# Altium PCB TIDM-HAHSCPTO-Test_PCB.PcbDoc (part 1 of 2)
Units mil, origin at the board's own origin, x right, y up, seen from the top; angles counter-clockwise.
Board outline 6700 x 4350 mil, 2 copper layers (Top Layer, Bottom Layer), stack 62 mil thick; 37 components, 162 nets, 491 pads, 55 vias.
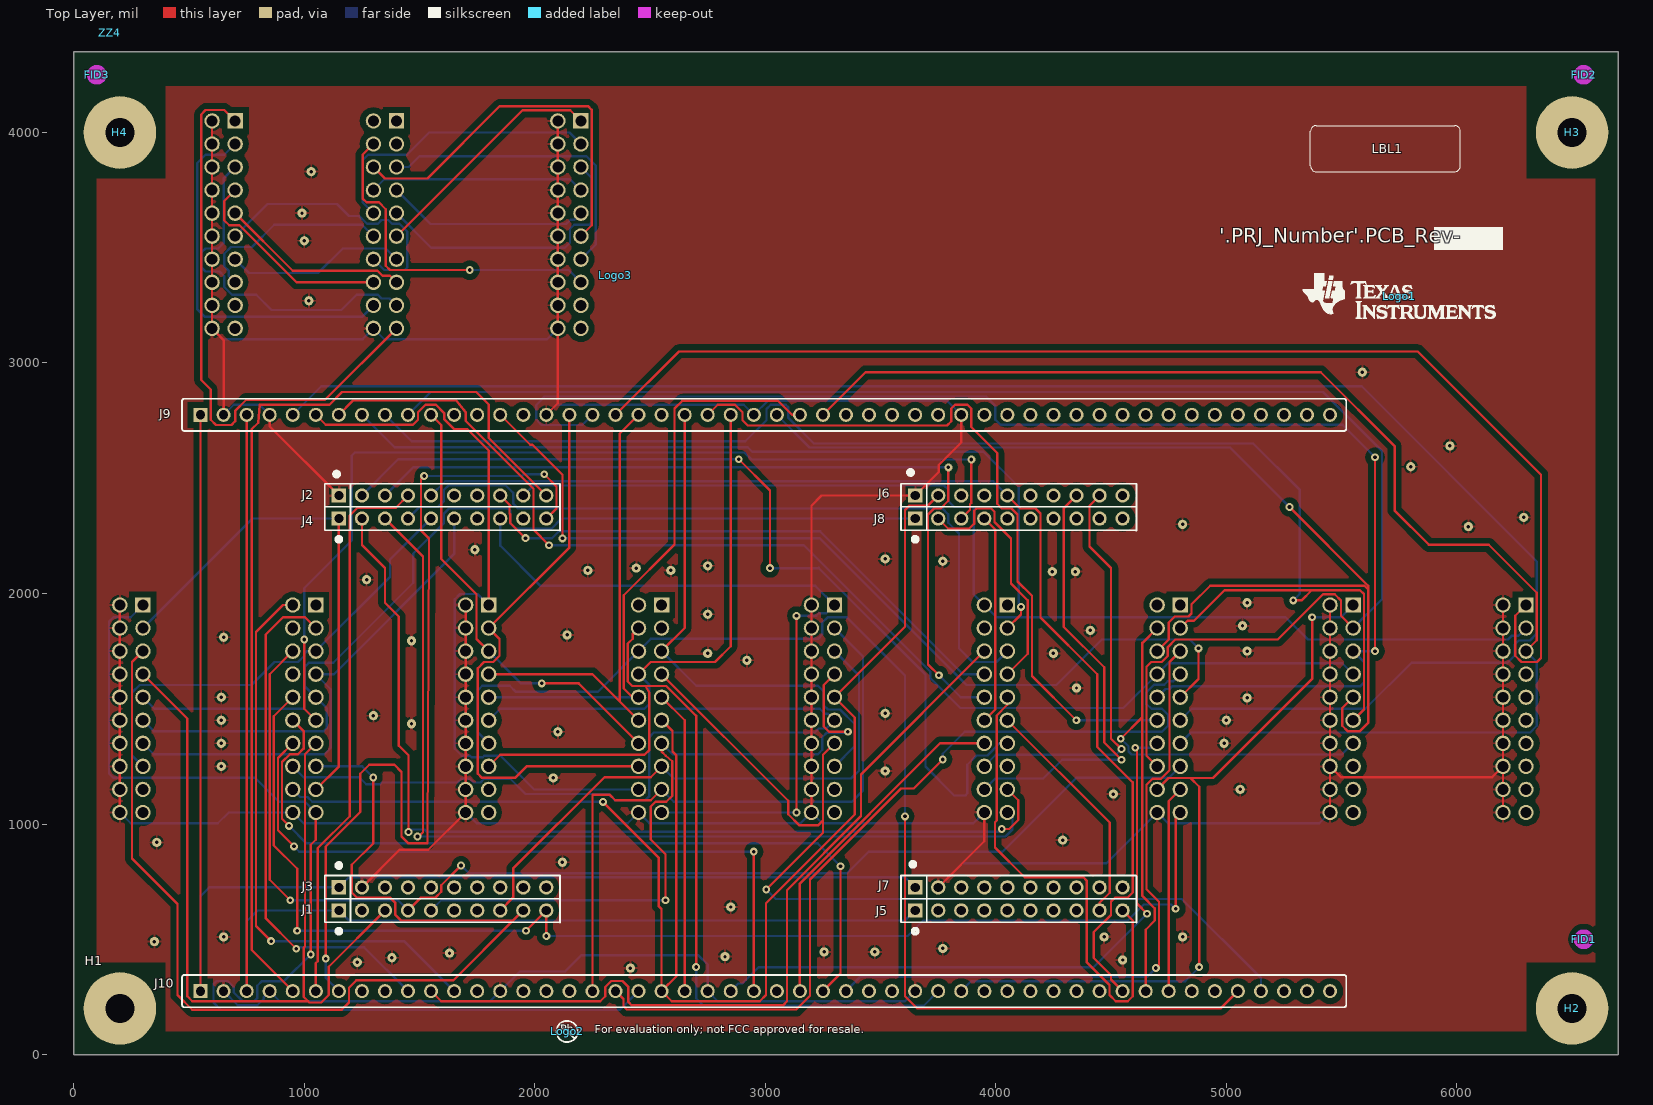
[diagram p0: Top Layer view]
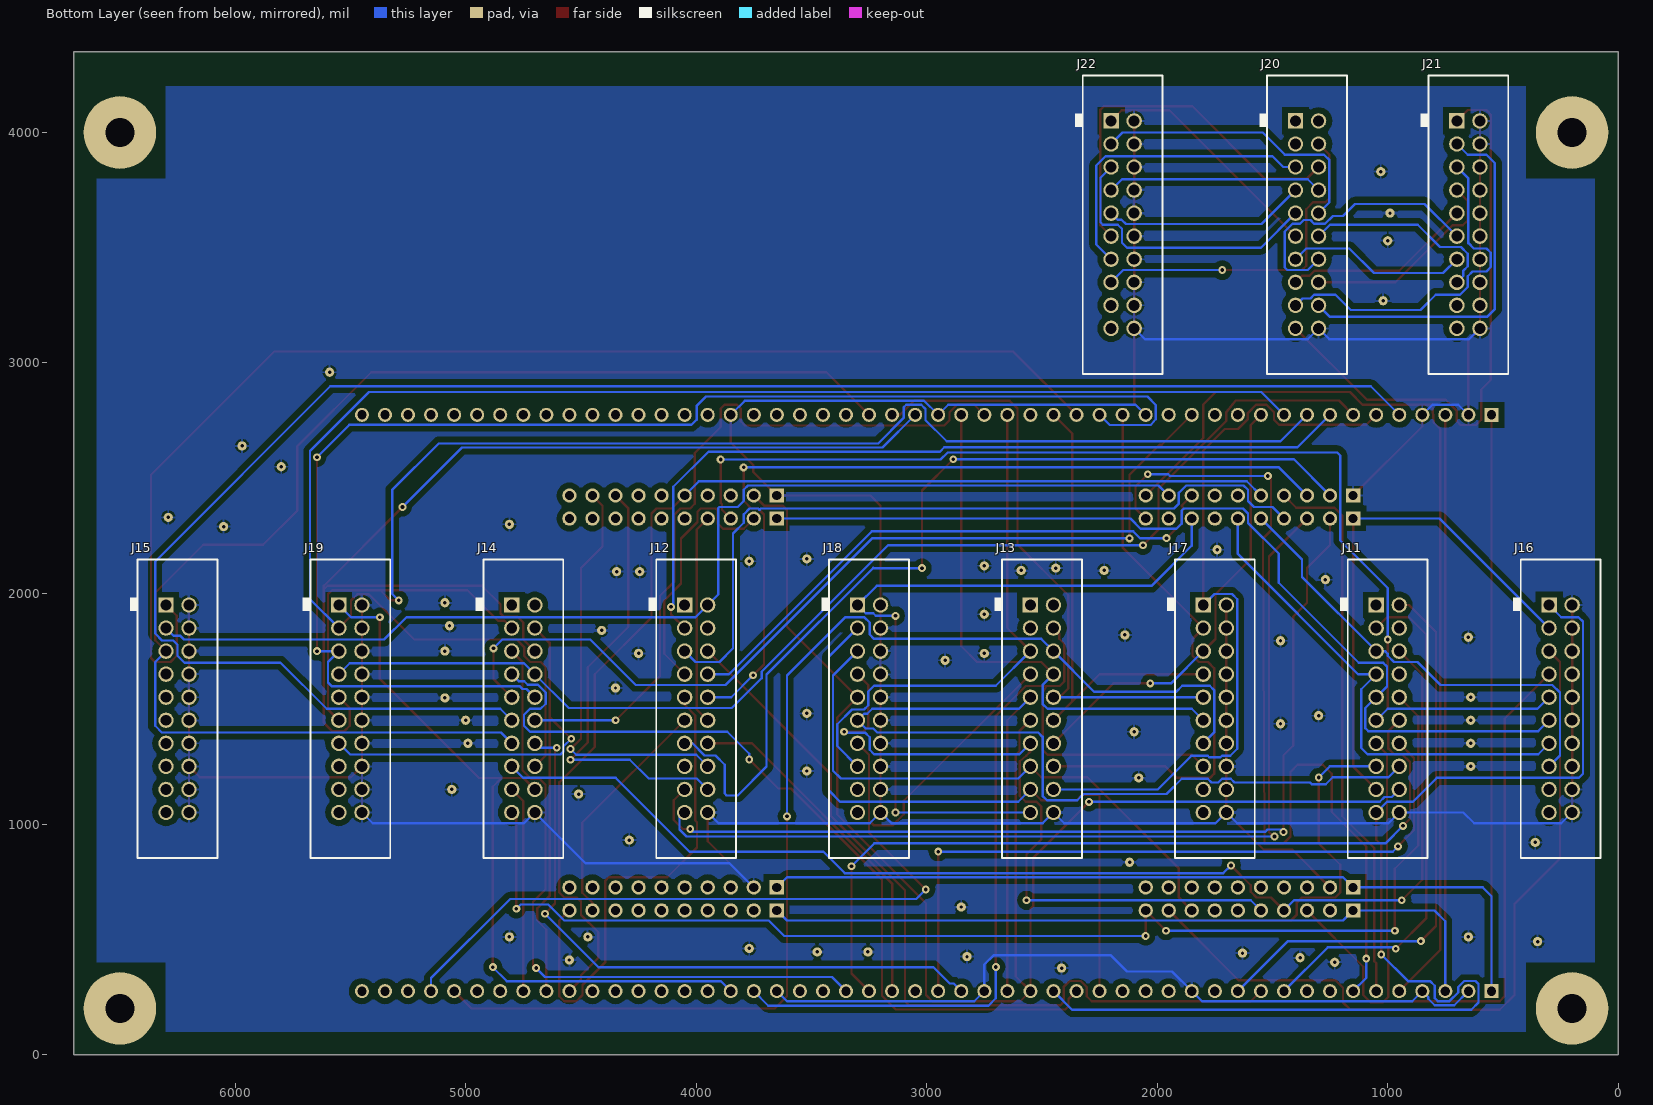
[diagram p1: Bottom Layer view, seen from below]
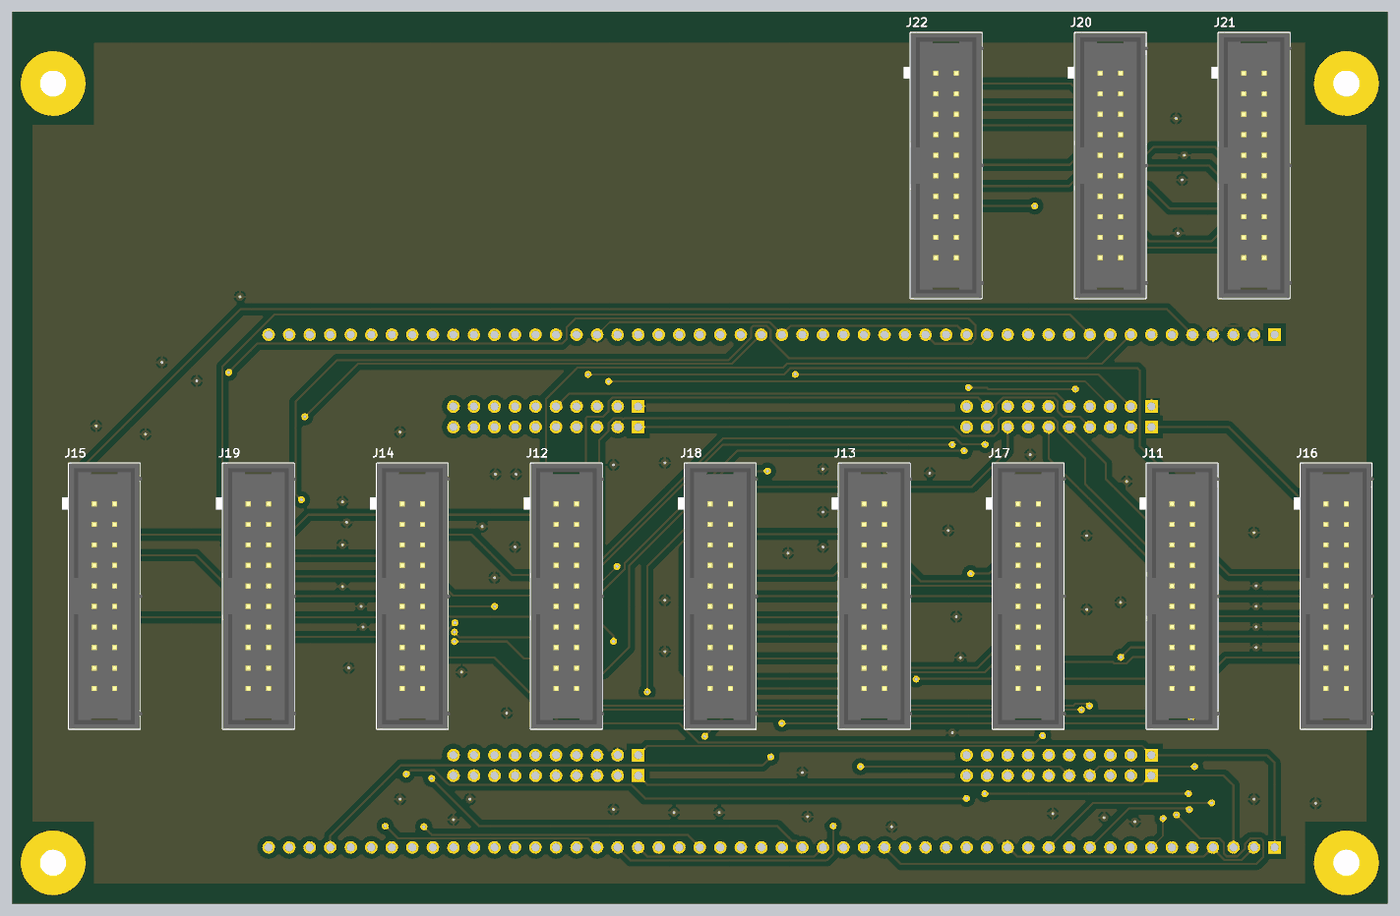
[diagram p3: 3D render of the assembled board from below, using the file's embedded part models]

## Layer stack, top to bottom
Top Solder: solder mask 0.4, Solder Resist, Dk 3.5
Top Layer: signal copper 1.4
Dielectric1: core 59.2, FR-4, Dk 4.8
Bottom Layer: signal copper 1.4
Bottom Solder: solder mask 0.4, Solder Resist, Dk 3.5

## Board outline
0,0 6700,0 6700,4350 0,4350

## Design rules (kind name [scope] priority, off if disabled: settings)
AcuteAngle [All] p1: minimum=4.50000000000000E+0001 checktracksonly=FALSE
AssemblyTestPointUsage [All] p1: valid=2
BoardOutlineClearance BoardOutlineClearance_MountingHoles [OnCopper and InComponentClass('Mounting Holes')] p1: gap=40
BoardOutlineClearance BoardOutlineClearance_Poly [OnCopper and InPoly] p2: gap=25
BoardOutlineClearance [OnCopper and Not InComponentClass('Logo') and not InComponentClass('FiducialMark') and not InRegion(1000,500,4000,800)] p3: gap=75
Clearance Clearance_Keepouts [((IsTrack Or IsArc) And Not InPoly) And IsFree and IsKeepOut vs ((IsTrack Or IsArc) And Not InPoly) And IsFree and IsKeepOut] p1: gap=0
Clearance Clearance_Poly [InPolygon] p2: gap=25
Clearance [All] p3: gap=7.87
ComponentClearance ComponentClearanceJ1J3 [InComponent('J1') vs InComponent('J3')] p1: gap=0 collisioncheckmode=3 verticalgap=10 showdistances=FALSE
ComponentClearance ComponentClearanceJ2J4 [InComponent('J2') vs InComponent('J4')] p2: gap=0 collisioncheckmode=3 verticalgap=10 showdistances=FALSE
ComponentClearance ComponentClearanceJ5J7 [InComponent('J5') vs InComponent('J7')] p3: gap=0 collisioncheckmode=3 verticalgap=10 showdistances=FALSE
ComponentClearance ComponentClearanceJ6J8 [InComponent('J6') vs InComponent('J8')] p4: gap=0 collisioncheckmode=3 verticalgap=10 showdistances=FALSE
ComponentClearance ComponentClearanceAll [All] p5: gap=10 collisioncheckmode=3 verticalgap=10 showdistances=FALSE
ComponentClearance ComponentClearance_MountingHoles_FiducialMarks [InComponentClass('Mounting Holes') vs InComponentClass('FiducialMark')] p6: gap=50 collisioncheckmode=3 verticalgap=10 showdistances=FALSE
ComponentClearance ComponentClearance_Shunt [InComponentClass('Header') vs InComponentClass('Shunt')] p7: gap=0 collisioncheckmode=3 verticalgap=0 showdistances=FALSE
ComponentClearance ComponentClearance_Logo [InComponentClass('Logo')] p8: gap=50 collisioncheckmode=3 verticalgap=10 showdistances=FALSE
ComponentClearance ComponentClearance_ScrewToNut [(HasFootprint('NY PMS 440 0025 PH')) vs (HasFootprint('Keystone_1902C'))] p9: gap=5 collisioncheckmode=3 verticalgap=10 showdistances=FALSE
ComponentClearance ComponentClearance_MountingHoles [InComponentClass('Mounting Holes')] p10: gap=250 collisioncheckmode=3 verticalgap=100000 showdistances=FALSE
ComponentClearance ComponentClearance_SmallPassives [HasFootprint('0201*') or HasFootprint('0402*') or HasFootprint('0508') or HasFootprint('0603*') or HasFootprint('0612') or HasFootprint('0805*') or HasFootprint('0815*') or HasFootprint('0830*') or HasFootprint('1206*') or HasFootprint('1210*') or HasFootprint('1808*') or HasFootprint('1812*') or HasFootprint('1825*') or HasFootprint('2010*') or HasFootprint('2220*') or HasFootprint('2225*') or HasFootprint('2512*') or HasFootprint('2728*') or HasFootprint('3518*') vs HasFootprint('0201*') or HasFootprint('0402*') or HasFootprint('0508') or HasFootprint('0603*') or HasFootprint('0612') or HasFootprint('0805*') or HasFootprint('0815*') or HasFootprint('0830*') or HasFootprint('1206*') or HasFootprint('1210*') or HasFootprint('1808*') or HasFootprint('1812*') or HasFootprint('1825*') or HasFootprint('2010*') or HasFootprint('2220*') or HasFootprint('2225*') or HasFootprint('2512*') or HasFootprint('2728*') or HasFootprint('3518*')] p11: gap=14.96 collisioncheckmode=3 verticalgap=10 showdistances=FALSE
ComponentClearance ComponentClearance_THtoSMT [IsThruComponent vs IsSMTComponent] p12: gap=40 collisioncheckmode=3 verticalgap=30 showdistances=FALSE
ComponentClearance ComponentClearance_THtoTH [IsThruComponent vs IsThruComponent] p13: gap=30 collisioncheckmode=3 verticalgap=30 showdistances=FALSE
DiffPairsRouting [All] p1: maxlimit=100 minlimit=10 mostfreqgap=10 toplayer_minwidth=15 toplayer_maxwidth=15 toplayer_prefwidth=15 bottomlayer_minwidth=15 bottomlayer_maxwidth=15 bottomlayer_prefwidth=15 maxuncoupledlength=1000
FabricationTestPointUsage TestPointUsage [All] p1: valid=2 allowmultiple=FALSE
FabricationTestpoint Testpoint [All] p1: side=3 testpointundercomponent=TRUE minsize=40 maxsize=100 preferedsize=60 minholesize=0 maxholesize=40 preferedholesize=32 testpointgrid=1 allowsidetop=TRUE allowsidebottom=TRUE usegrid=TRUE gridtolerance=0.01
FanoutControl Fanout_LCC [IsLCC] p1: bgadir=Out bgaviamode=Centered fanoutstyle=Auto fanoutdirection=Alternating viagrid=1 // Fanout_LCC (Default Rule)
FanoutControl Fanout_BGA [IsBGA] p2: bgadir=Out bgaviamode=Centered fanoutstyle=Auto fanoutdirection=Alternating viagrid=1 // Fanout_BGA (Default Rule)
FanoutControl Fanout_Default [All] p4: bgadir=Out bgaviamode=Centered fanoutstyle=Auto fanoutdirection=Alternating viagrid=1 // Fanout_Default (Default Rule)
FanoutControl Fanout_Small [(CompPinCount < 5)] p5: bgadir=Out bgaviamode=Centered fanoutstyle=Auto fanoutdirection=OutThenIn viagrid=1 // Fanout_Small (Default Rule)
HoleSize [All] p1: absolutevalues=TRUE maxlimit=251 minlimit=7.87 maxpercent=80.000 minpercent=20.000
MinimumAnnularRing MinimumAnnularRing_ThermalPadVias [IsVia and InAnyComponent] p1: minimumring=5.91
MinimumAnnularRing [All] p2: minimumring=8
MinimumSolderMaskSliver MinimumSolderMaskSliver_Logo [InComponentClass('Logo') vs InComponentClass('Logo')] p1: minsoldermaskwidth=0.7
MinimumSolderMaskSliver [All] p2: minsoldermaskwidth=3.94
PlaneConnect [All] p1: planeconnectstyle=Relief reliefexpansion=10 reliefentries=4 reliefconductorwidth=10 reliefairgap=10
PolygonConnect [All] p1: connectstyle=Relief reliefconductorwidth=10 reliefentries=4 polygonreliefangle="90 Angle" airgapwidth=10
RoutingVias ThermalPadVias [IsVia and InAnyComponent] p1: holewidth=7.87 width=19.68 viastyle="Through Hole" minholewidth=7.87 minwidth=19.68 maxholewidth=12.99 maxwidth=23.62
RoutingVias [All] p2: holewidth=16 width=34 viastyle="Through Hole" minholewidth=7.87 minwidth=26 maxholewidth=40 maxwidth=65
SilkToBoardRegionClearance [Not ((IsComment or IsDesignator) And (Hide <> 'False')) and not InRegion(1000,500,4000,800)] p1:
SilkToSilkClearance SilkToSilkClearance_Pb-FreeLogo [(HasFootprint('Pb-Free_Overlay_Medium') OR HasFootprint('Pb-Free_Overlay_Small')) vs (HasFootprint('Pb-Free_Overlay_Medium') OR HasFootprint('Pb-Free_Overlay_Small'))] p1: silktosilkclearance=0
SilkToSilkClearance [All] p2: silktosilkclearance=4
SilkToSolderMaskClearance SilkToComponentPadClearance [IsPad and InAnycomponent] p1: minsilkscreentomaskgap=5 clearancetoexposedcopper=TRUE
SilkToSolderMaskClearance "Silk to Solder Mask Opening" [All] p2: minsilkscreentomaskgap=4 clearancetoexposedcopper=FALSE
SolderMaskExpansion [All] p1: expansion=1.97
Width [All] p1: maxlimit=100 minlimit=6 preferedwidth=10 checkconnectedcopper=TRUE
15 further rules are at their usual default settings.

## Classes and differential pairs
component class "Mounting Holes": H1 H2 H3 H4
component class FiducialMark: FID1 FID2 FID3
component class Logo: Logo1
component class TIDM-HAHSCPTO-Test_Hw: FID1 FID2 FID3 H1 H2 H3 H4 LBL1 Logo1 Logo2 Logo3 ZZ1 ZZ2 ZZ3 ZZ4
component class AssemblyNote: ZZ1 ZZ2 ZZ3 ZZ4
component class Label: LBL1
component class TIDM-HAHSCPTO-Test_BoosterPack: J1 J2 J3 J4 J5 J6 J7 J8
component class TIDM-HAHSCPTO-Test_LogicAna: J11 J12 J13 J14
component class TIDM-HAHSCPTO-Test_Monitor: J20 J21 J22
component class TIDM-HAHSCPTO-Test_PatGen: J15 J16 J17 J18 J19
component class TIDM-HAHSCPTO-Test_Proto: J9 J10

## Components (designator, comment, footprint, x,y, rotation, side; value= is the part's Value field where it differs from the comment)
FID1 "Fiducial" Fiducial10-20 6550,500 r0 top
FID2 "Fiducial" Fiducial10-20 6550,4250 r0 top
FID3 "Fiducial" Fiducial10-20 100,4250 r0 top
H1 "NY PMS 440 0025 PH" "NY PMS 440 0025 PH" 200,200 r0 top
H2 "NY PMS 440 0025 PH" "NY PMS 440 0025 PH" 6500,200 r0 top
H3 "NY PMS 440 0025 PH" "NY PMS 440 0025 PH" 6500,4000 r0 top
H4 "NY PMS 440 0025 PH" "NY PMS 440 0025 PH" 200,4000 r0 top
J1 "PPTC101LFBN-RC" CONN_PPTC101LFBN-RC 1600,625 r180 top
J2 "PPTC101LFBN-RC" CONN_PPTC101LFBN-RC 1600,2425 r180 top
J3 "PPTC101LFBN-RC" CONN_PPTC101LFBN-RC 1600,725 r180 top
J4 "PPTC101LFBN-RC" CONN_PPTC101LFBN-RC 1600,2325 r180 top
J5 "PPTC101LFBN-RC" CONN_PPTC101LFBN-RC 4100,625 r180 top
J6 "PPTC101LFBN-RC" CONN_PPTC101LFBN-RC 4100,2425 r180 top
J7 "PPTC101LFBN-RC" CONN_PPTC101LFBN-RC 4100,725 r180 top
J8 "PPTC101LFBN-RC" CONN_PPTC101LFBN-RC 4100,2325 r180 top
J9 "SFH11-PBPC-D25-ST-BK" SFH11-PBPC-D25-ST-BK 3000,2775 r0 top
J10 "SFH11-PBPC-D25-ST-BK" SFH11-PBPC-D25-ST-BK 3000,275 r0 top
J11 "SBH11-PBPC-D10-ST-BK" Sullins_SBH11-xxxC-D10-ST 1000,1500 r180 bottom
J12 "SBH11-PBPC-D10-ST-BK" Sullins_SBH11-xxxC-D10-ST 4000,1500 r180 bottom
J13 "SBH11-PBPC-D10-ST-BK" Sullins_SBH11-xxxC-D10-ST 2500,1500 r180 bottom
J14 "SBH11-PBPC-D10-ST-BK" Sullins_SBH11-xxxC-D10-ST 4750,1500 r180 bottom
J15 "SBH11-PBPC-D10-ST-BK" Sullins_SBH11-xxxC-D10-ST 6250,1500 r180 bottom
J16 "SBH11-PBPC-D10-ST-BK" Sullins_SBH11-xxxC-D10-ST 250,1500 r180 bottom
J17 "SBH11-PBPC-D10-ST-BK" Sullins_SBH11-xxxC-D10-ST 1750,1500 r180 bottom
J18 "SBH11-PBPC-D10-ST-BK" Sullins_SBH11-xxxC-D10-ST 3250,1500 r180 bottom
J19 "SBH11-PBPC-D10-ST-BK" Sullins_SBH11-xxxC-D10-ST 5500,1500 r180 bottom
J20 "SBH11-PBPC-D10-ST-BK" Sullins_SBH11-xxxC-D10-ST 1350,3600 r180 bottom
J21 "SBH11-PBPC-D10-ST-BK" Sullins_SBH11-xxxC-D10-ST 650,3600 r180 bottom
J22 "SBH11-PBPC-D10-ST-BK" Sullins_SBH11-xxxC-D10-ST 2150,3600 r180 bottom
LBL1 "Size: 0.65\" x 0.20 \"" Label_650x200 5690,3930 r0 top
Logo1 "Texas Instruments" TI_Stacked_Overlay_Small 5750,3290 r0 top
Logo2 "Pb-Free Symbol" Pb-Free_Overlay_Small 2140,100 r0 top
Logo3 "FCC disclaimer" FCC_disclaimer 2350,3380 r0 top
ZZ1 "This Assembly Note is for PCB labels only" AssemblyNoteLabel 155,4718 r0 top
ZZ2 "These assemblies are ESD sensitive, ESD precautions shall be observed." AssemblyNote 155,4609.11 r0 top
ZZ3 "These assemblies must be clean and free from flux and all contaminants. Use of no clean flux is not acceptable." AssemblyNote 155,4520.56 r0 top
ZZ4 "These assemblies must comply with workmanship standards IPC-A-610 Class 2, unless otherwise specified." AssemblyNote 155,4432 r0 top

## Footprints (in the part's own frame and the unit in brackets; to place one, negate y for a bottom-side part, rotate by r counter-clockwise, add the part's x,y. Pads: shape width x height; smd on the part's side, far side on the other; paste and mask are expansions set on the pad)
AssemblyNote [mil] "Assembly Note"
AssemblyNoteLabel [mil] "Assembly Note for PCB Labels"
CONN_PPTC101LFBN-RC [mil] "SULLINS"
  rect 62x62 hole 40: 1(450,0)
  round 62 hole 40.16: 2(350,0) 3(250,0) 4(150,0) 5(50,0) 6(-50,0) 7(-150,0) 8(-250,0) 9(-350,0) 10(-450,0)
  silkscreen extent -510,-51 511,100, body extent -510,-50 510,50, height 336
FCC_disclaimer [mil]
Fiducial10-20 [mm]
  round 1 smd mask+0.5: 1(0,0)
  Top Layer keep-out circle w1.178: c0,0 r0.5
Label_650x200 [mil] "Thermal Transfer Label"
  silkscreen extent -325,-100 325,100, body extent -325,-100 325,100, height 1
"NY PMS 440 0025 PH" [mm] "4-40 nylon screw and mounting hole"
  round 8 hole 3.2: 1(0,0)
  body extent -3.3,-3.3 3.3,3.3, height 2.69
Pb-Free_Overlay_Small [mil]
  silkscreen extent -46,-46 46,46
SFH11-PBPC-D25-ST-BK [mm]
  rect 1.55x1.55 hole 1.02: 1(-62.23,0)
  round 1.55 hole 1.02: 2(-59.69,0) 3(-57.15,0) 4(-54.61,0) 5(-52.07,0) 6(-49.53,0) 7(-46.99,0) 8(-44.45,0) 9(-41.91,0) 10(-39.37,0) 11(-36.83,0) 12(-34.29,0) 13(-31.75,0) 14(-29.21,0) 15(-26.67,0) 16(-24.13,0) 17(-21.59,0) 18(-19.05,0) 19(-16.51,0) 20(-13.97,0) 21(-11.43,0) 22(-8.89,0) 23(-6.35,0) 24(-3.81,0) 25(-1.27,0) 26(1.27,0) 27(3.81,0) 28(6.35,0) 29(8.89,0) 30(11.43,0) 31(13.97,0) 32(16.51,0) 33(19.05,0) 34(21.59,0) 35(24.13,0) 36(26.67,0) 37(29.21,0) 38(31.75,0) 39(34.29,0) 40(36.83,0) 41(39.37,0) 42(41.91,0) 43(44.45,0) 44(46.99,0) 45(49.53,0) 46(52.07,0) 47(54.61,0) 48(57.15,0) 49(59.69,0) 50(62.23,0)
  silkscreen extent -64.26,-1.78 64.01,1.78
Sullins_SBH11-xxxC-D10-ST [mm] "Header (Shrouded), 2.54mm, 10x2, TH"
  rect 1.7x1.7 hole 1.2: 1(-1.27,11.43)
  round 1.7 hole 1.2: 2(1.27,11.43) 3(-1.27,8.89) 4(1.27,8.89) 5(-1.27,6.35) 6(1.27,6.35) 7(-1.27,3.81) 8(1.27,3.81) 9(-1.27,1.27) 10(1.27,1.27) 11(-1.27,-1.27) 12(1.27,-1.27) 13(-1.27,-3.81) 14(1.27,-3.81) 15(-1.27,-6.35) 16(1.27,-6.35) 17(-1.27,-8.89) 18(1.27,-8.89) 19(-1.27,-11.43) 20(1.27,-11.43)
  silkscreen extent -5.25,-16.45 4.4,16.45, body extent -4.4,-16.45 4.7,16.45, height 9.11
TI_Stacked_Overlay_Small [mil]
  silkscreen extent -418,-98 418,98

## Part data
FID1 FID2 FID3: "Fiducial mark.  There is nothing to buy or mount."
H1 H2 H3 H4: "Machine Screw, Round, #4-40 x 1/4, Nylon, Philips panhead"
J1 J2 J3 J4 J5 J6 J7 J8: "Receptacle, 100mil, 10x1, Tin, TH"
J9 J10: ".100\" 1 Row, Thru Hole with Polarizing Key"
J11 J12 J13 J14 J15 J16 J17 J18 J19 J20 J21 J22: "Header (Shrouded), 2.54mm, 10x2, Gold, Black, TH"
LBL1: library part THT-14-423-10, "Thermal Transfer Printable Labels, 0.650\" W x 0.200\" H - 10,000 per roll"
Logo1: library part TI_Logo, "Texas Instrument Corporate Signature"
Logo2: library part Pb-Free
Logo3: library part FCC_disclaimer, "FCC_disclaimer"
ZZ1: library part AssemblyNoteLabel
ZZ2 ZZ3 ZZ4: library part AssemblyNote

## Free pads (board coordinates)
  round 40 hole 15: 2(650,1810) 3(2140,1820) 4(1300,1470) 5(360,920) 5(990,3650) 5(1000,3530) 5(1020,3270) 5(1030,3830) 5(1465,1435) 5(1465,1795) 5(1740,2190) 5(2080,1200) 5(2100,1400) 5(2120,834) 5(2415,375) 5(2440,2110) 5(2590,2100) 5(2750,1740) 5(2750,1910) 5(2750,2120) 5(2825,425) 5(2920,1710) 5(3255,445) 5(3475,445) 5(3770,460) 5(4245,2095) 5(4345,2095) 5(4990,1350) 5(5000,1450) 5(5060,1150) 5(5070,1860) 5(5090,1547) 5(5090,1750) 5(5090,1960) 5(5590,2960) 5(5800,2550) 5(5970,2640) 5(6050,2290) 5(6290,2330) 6(2850,640) 7(4810,2300) 8(4350,1590) 9(3520,1480) 10(3520,1230) 11(4510,1130) 12(4290,930) 13(4810,510) 14(4550,410) 15(4470,510) 16(640,1250) 17(640,1450) 18(640,1350) 19(640,1550) 20(350,490) 21(650,510) 22(1630,440) 23(1380,420) 24(1230,400) 25(2230,2100) 27(1270,2060) 28(4250,1740) 29(4410,1840) 30(3520,2150) 32(3770,2140)

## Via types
v1: diameter 34, hole 16, Top Layer to Bottom Layer, 55 vias

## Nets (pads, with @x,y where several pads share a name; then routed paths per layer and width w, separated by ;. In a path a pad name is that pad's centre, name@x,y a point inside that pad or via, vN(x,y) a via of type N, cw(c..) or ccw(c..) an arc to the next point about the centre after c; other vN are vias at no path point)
+3V3: J1.1 J5.1 J9.3 J10.3 | length 5758.9
  Top Layer w10: J10.3@750,275 J9.3@750,2775
  Bottom Layer w10: J10.3@750,275 750,578 797,625 J1.1@1150,625 1194,581 3606,581 J5.1@3650,625
+5V: J3.1 J7.1 J9.1 J10.1 | length 6064.2
  Top Layer w10: J10.1@550,275 J9.1@550,2775
  Bottom Layer w10: J10.1@550,275 550,687 588,725 J3.1@1150,725 1194,769 3606,769 J7.1@3650,725
AD1EVT/MII_RX_ER/RMII_RX_ER/NTZ1_1: J8.9
AD1IN_0: J3.3
AD1IN_1: J5.6
AD1IN_2: J7.4
AD1IN_3: J7.5
AD1IN_4: J7.7
AD1IN_5: J9.47
AD1IN_6: J9.48
AD1IN_7: J3.4
AD1IN_8/AD2IN_8: J9.43
AD1IN_9/AD2IN_9: J5.2
AD1IN_10/AD2IN_10: J7.3
AD1IN_11/AD2IN_11: J7.6
AD1IN_12/AD2IN_12: J7.8
AD1IN_13/AD2IN_13: J9.46
AD1IN_14/AD2IN_14: J9.44
AD1IN_15/AD2IN_15: J9.41
AD1IN_16/AD2IN_0: J1.2
AD1IN_17/AD2IN_1: J1.6
AD1IN_18/AD2IN_2: J3.5
AD1IN_19/AD2IN_3: J3.6
AD1IN_20/AD2IN_4: J3.7
AD1IN_21/AD2IN_5: J3.8
AD1IN_22/AD2IN_6: J9.45
AD1IN_23/AD2IN_7: J9.42
AD1IN_24: J9.49
AD1IN_25: J9.50
AD1IN_26: J9.31
AD1IN_27: J9.32
AD1IN_28: J9.33
AD1IN_29: J9.35
AD1IN_30: J9.36
AD1IN_31: J9.37
AD2EVT: J9.40
AD2IN_23: J9.29
AD2IN_24: J9.30
ADREFHI: J9.39
ADREFLO: J9.38
DCAN1RX: J10.44
DCAN1TX: J10.45
DCAN2RX: J9.12
DCAN2TX: J9.13
DCAN3RX: J10.13
DCAN3TX: J10.15
ECLK1T: J9.19 J15.1 | length 5515.2
  Top Layer w10: J9.19@2350,2775 2625,3050 5830,3050 6365,2515 6365,1720 6348,1703 6280,1703 6253,1730 6253,1903 J15.1@6300,1950
EPWM1A: J10.17
EPWM1B: J10.16
FRAYRX1: J10.35
FRAYRX2: J10.38
FRAYTX1/GIOA_2: J10.36
FRAYTX2/GIOB_0: J10.39
FRAYTXEN1/GIOB_1: J10.37
FRAYTXEN2/GIOB_2: J10.40
GIOA_0: J4.10 J10.7 | length 4012
  Top Layer w10: v1(1093,416) 1093,902 1243,1052 1243,1218 1282,1257 1391.25,1257 1422.13,1226.13 1422.13,945.71 1452,915.83 1534.15,915.83 1540.61,2238.39 1506,2273 1506,2496 v1(1520,2510) ; v1(2041,2517) 2094,2464 2094,2369 J4.10@2050,2325
  Bottom Layer w10: v1(1093,416) 1093,332 J10.7@1150,275 ; v1(1520,2510) 1945,2510 1952,2517 v1(2041,2517)
GIOA_1: J4.9
GIOA_2/N2HET2_0/EQEP2I: J4.8 J13.19 J18.1 | length 3296.5
  Top Layer w10: v1(3135,1050) v1(3135,1903)
  Bottom Layer w10: J4.8@1850,2325 1850,2207.64 2024.64,2033 3217,2033 J18.1@3300,1950 3264.21,1914.21 3232.13,1914.21 3220.91,1903 v1(3135,1903) ; J13.19@2550,1050 v1(3135,1050)
GIOA_3/N2HET2_2: J10.18 J13.17 J18.3 | length 2851.9
  Top Layer w10: J10.18@2250,275 2250,1125 2251.3,1126.3 2325.74,1126.3 2349.1,1102.94 2502.94,1102.94 J13.17@2550,1150
  Bottom Layer w10: J13.17@2550,1150 2603,1097 3376,1097 3423.96,1144.96 3423.96,1726.04 J18.3@3300,1850
GIOA_4: J9.15
GIOA_5/EXTCLKIN/EPWM1A: J4.7
GIOA_6/N2HET2_4/EPWM1B: J1.8 J13.15 J18.5 | length 2487.6
  Top Layer w10: J1.8@1850,625 1906,681 1906,806.83 2302.17,1203 2503,1203 J13.15@2550,1250
  Bottom Layer w10: J13.15@2550,1250 2603,1197 3372,1197 3406.09,1231.09 3406.09,1643.91 J18.5@3300,1750
GIOA_7/N2HET2_6/EPWM2A: J1.5 J13.13 J18.7 | length 3089.6
  Top Layer w10: J13.13@2550,1350 2550,1314 2567.66,1296.34 2596.34,1272 2596.34,1122 2570.68,1096.34 2524,1096.34 2503,1075.34 2503,933 2567,869 v1(2567,669) ; J18.7@3300,1650 3253,1603 3253,1423 3276,1400 v1(3358,1400)
  Bottom Layer w10: J1.5@1550,625 1594,669 v1(2567,669) ; J13.13@2550,1350 2597,1303 3228,1303 3247,1322 3247,1376 3267.34,1396.34 3354.34,1396.34 v1(3358,1400)
GIOB_0: J8.8
GIOB_1: J8.7
GIOB_2/DCAN4TX: J2.10 J10.5 | length 4166.3
  Top Layer w10: J10.5@950,275 772,453 772,2713 800,2741 807,2819 1109,2819 1164,2874 1746,2874 1800,2820 1800,2675 J2.10@2050,2425
GIOB_3/DCAN4RX: J2.4 J10.6 | length 2412.9
  Top Layer w10: J10.6@1050,275 1050,396.64 1058.31,404.96 1058.31,895.31 1197,1034 1197,2338 1231,2372 1397,2372 J2.4@1450,2425
GND: J2.1 J3.2 J6.1 J7.2 J9.2 J9.4 J9.16 J9.25 J9.34 J10.2 J10.4 J10.14 J10.23 J10.32 J11.20 J12.20 J13.20 J14.20 J15.2 J15.4 J15.6 J15.8 J15.10 J15.12 J15.14 J15.16 J15.18 J15.20 J16.2 J16.4 J16.6 J16.8 J16.10 J16.12 J16.14 J16.16 J16.18 J16.20 J17.2 J17.4 J17.6 J17.8 J17.10 J17.12 J17.14 J17.16 J17.18 J17.20 J18.2 J18.4 J18.6 J18.8 J18.10 J18.12 J18.14 J18.16 J18.18 J18.20 J19.2 J19.4 J19.6 J19.8 J19.10 J19.12 J19.14 J19.16 J19.18 J19.20 J20.20 J21.2 J21.4 J21.6 J21.8 J21.10 J21.12 J21.14 J21.16 J21.18 J21.20 J22.2 J22.4 J22.6 J22.8 J22.10 J22.12 J22.14 J22.16 J22.18 J22.20 pad.2 pad.3 pad.4 pad.5 pad.6 pad.7 pad.8 pad.9 pad.10 pad.11 pad.12 pad.13 pad.14 pad.15 pad.16 pad.17 pad.18 pad.19 pad.20 pad.21 pad.22 pad.23 pad.24 pad.25 pad.27 pad.28 pad.29 pad.30 pad.32 | length 23522.7
  Top Layer w10: J16.20@200,1050 J16.18@200,1150 J16.16@200,1250 J16.14@200,1350 J16.12@200,1450 J16.10@200,1550 J16.8@200,1650 J16.6@200,1750 J16.4@200,1850 J16.2@200,1950 ; J21.2@600,4050 J21.4@600,3950 J21.6@600,3850 J21.8@600,3750 J21.10@600,3650 J21.12@600,3550 J21.14@600,3450 J21.16@600,3350 J21.18@600,3250 J21.20@600,3150 650,3100 J9.2@650,2775 ; J9.4@850,2775 850,2725 J2.1@1150,2425 ; J3.2@1250,725 1413,888 1538,888 J17.20@1700,1050 J17.18@1700,1150 J17.16@1700,1250 J17.14@1700,1350 J17.12@1700,1450 J17.10@1700,1550 J17.8@1700,1650 J17.6@1700,1750 J17.4@1700,1850 J17.2@1700,1950 ; J9.16@2050,2775 2100,2825 J22.20@2100,3150 J22.18@2100,3250 J22.16@2100,3350 J22.14@2100,3450 J22.12@2100,3550 J22.10@2100,3650 J22.8@2100,3750 J22.6@2100,3850 J22.4@2100,3950 J22.2@2100,4050 ; J18.20@3200,1050 J18.18@3200,1150 J18.16@3200,1250 J18.14@3200,1350 J18.12@3200,1450 J18.10@3200,1550 J18.8@3200,1650 J18.6@3200,1750 J18.4@3200,1850 J18.2@3200,1950 3200,2381 3244,2425 J6.1@3650,2425 3752.05,2527.05 3752.05,2556.94 3850,2654.9 J9.34@3850,2775 ; J7.2@3750,725 3950,925 J12.20@3950,1050 ; J19.20@5450,1050 J19.18@5450,1150 J19.16@5450,1250 ; J19.2@5450,1950 J19.4@5450,1850 J19.6@5450,1750 J19.8@5450,1650 J19.10@5450,1550 J19.12@5450,1450 J19.14@5450,1350 J19.16@5450,1250 ; J15.20@6200,1050 J15.18@6200,1150 J15.16@6200,1250 ; J15.2@6200,1950 J15.4@6200,1850 J15.6@6200,1750 J15.8@6200,1650 J15.10@6200,1550 J15.12@6200,1450 J15.14@6200,1350 J15.16@6200,1250 ; J19.16@5450,1250 5497,1203 6153,1203 J15.16@6200,1250
  Bottom Layer w10: J16.20@200,1050 247,1003 625,1003 672,1050 J11.20@950,1050 997,1003 1653,1003 J17.20@1700,1050 1747,1003 2403,1003 J13.20@2450,1050 2497,1003 3153,1003 J18.20@3200,1050 3247,1003 3903,1003 J12.20@3950,1050 ; J21.20@600,3150 647,3103 1253,3103 J20.20@1300,3150 1347,3103 2053,3103 J22.20@2100,3150 ; J10.2@650,275 711.26,213.74 796.23,213.74 824.49,242 824.49,249.49 J10.4@850,275 894,231 1806,231 J10.14@1850,275 1935.26,360.26 2130.45,360.26 2200.18,430 2710,430 2750,390 J10.23@2750,275 2794,231 3606,231 J10.32@3650,275 ; J9.2@650,2775 694,2819 806,2819 J9.4@850,2775 ; J9.16@2050,2775 2094,2819 2906,2819 J9.25@2950,2775 3011.26,2836.26 3788.74,2836.26 J9.34@3850,2775 ; J7.2@3750,725 3855,830 4480,830 J14.20@4700,1050 4747,1003 5403,1003 J19.20@5450,1050
HERCULES_NRST: J2.5 J6.5 J10.41 | length 5119.2
  Top Layer w10: J6.5@4050,2425 4106.13,2368.87 4172,2368.87 4193.87,2347 4193.87,1896.13 4440,1650 4440,1334.5 4593.87,1180.63 4593.87,703 4572,681.13 4517.87,681.13 4500,663.25 4500,605.82 4424.13,529.96 4424.13,419.91 4500,344.05 4500,325 J10.41@4550,275
  Bottom Layer w10: J2.5@1550,2425 1611.75,2486.75 3988.25,2486.75 J6.5@4050,2425
LIN1RX: J5.3
LIN1TX: J5.4
MIBSPI1CLK: J5.7
MIBSPI1NCS_0/MIBSPI1SOMI_1/MII_TXD_2/ECAP6: J6.3
MIBSPI1NCS_1/MII_COL/N2HET1_17/EQEP1S: J6.8 J12.18 | length 1921.6
  Top Layer w10: J6.8@4350,2425 4294,2369 4294,1856 4470,1680 4470,1354 v1(4545,1279)
  Bottom Layer w10: J12.18@3950,1150 3997,1197 4206,1197 4288,1279 v1(4545,1279)
MIBSPI1NCS_2/MDIO/N2HET1_19: J6.9 J12.16 | length 1801.9
  Top Layer w10: J6.9@4450,2425 4406,2381 4406,2204 4500,2110 4500,1370 v1(4545,1325)
  Bottom Layer w10: J12.16@3950,1250 4000,1300 4520,1300 v1(4545,1325)
MIBSPI1NCS_3/N2HET1_21/NTZ1_3: J10.27 J12.14 | length 1518.7
  Top Layer w10: J10.27@3150,275 3150,741.73 3758.27,1350 J12.14@3950,1350
MIBSPI1NCS_4: J10.30
MIBSPI1NCS_5: J10.31
MIBSPI1NENA/MII_RXD_2/N2HET1_23/ECAP4: J8.4 J12.12 | length 913.9
  Top Layer w10: J12.12@3950,1450 3997,1497 3997,2278 J8.4@3950,2325
MIBSPI1SIMO_0: J6.6
MIBSPI1SOMI_0: J6.7
MIBSPI3CLK/AD1EXT_SEL_1/EQEP1A: J1.7
MIBSPI3NCS_0/AD2EVT/EQEP1I: J5.5
MIBSPI3NCS_1/MDCLK/N2HET1_25: J2.3 J12.10 | length 3705.8
  Top Layer w10: v1(3753,1645) 3706,1692 3706,2343.05 3731.83,2368.87 3760.87,2368.87 3794,2402 v1(3794,2547)
  Bottom Layer w10: J2.3@1350,2425 1472,2547 v1(3794,2547) ; v1(3753,1645) 3848,1550 J12.10@3950,1550
MIBSPI3NCS_2/I2C1_SDA/N2HET1_27/NTZ1_2: J2.8 J12.8 | length 2492.6
  Top Layer w10: J2.8@1850,2425 1894,2381 1890,2377 1890,2347.05 1893.87,2343.17 1893.87,2306.13 v1(1960,2240)
  Bottom Layer w10: v1(1960,2240) 2074.07,2240 2103.41,2269.34 3238.66,2269.34 3858,1650 J12.8@3950,1650
MIBSPI3NCS_3/I2C1_SCL/N2HET1_29/NTZ1_1: J2.9 J12.2 J15.3 | length 4914.3
  Bottom Layer w10: J2.9@1950,2425 1993.87,2468.87 3775.13,2468.87 3794,2450 3794,2401 3820,2375 3900,2375 3904,2371 3904,1996 J12.2@3950,1950 4003,1897 5257,1897 5354,1800 6221.57,1800 6237.57,1816 6266,1816 J15.3@6300,1850
MIBSPI3NENA/MIBSPI3NCS_5/N2HET1_31/EQEP1B: J5.8
MIBSPI3SIMO/AD1EXT_SEL_0/ECAP3: J2.6
MIBSPI3SOMI/AD1EXT_ENA/ECAP2: J2.7
MIBSPI5CLK/DMM_DATA_4/MII_TXEN/RMII_TXEN: J8.10
MIBSPI5NCS_0/DMM_DATA_5/EPWM4A: J10.26
MIBSPI5NENA/DMM_DATA_7/MII_RXD_3/ECAP5: J8.5
MIBSPI5SIMO_0/DMM_DATA_8/MII_TXD_1/RMII_TXD_1: J6.4
MIBSPI5SOMI_0/DMM_DATA_12/MII_TXD_0/RMII_TXD_0: J6.10
MON0: J20.19 J21.1 | length 2530.8
  Top Layer w10: J21.1@700,4050 653,4097 572,4097 553,4078 553,2926 594,2885 594,2754 617,2731 684,2731 700,2747 700,2792 748,2840 1090,2840 J20.19@1400,3150
MON1: J20.18 J21.3 | length 1631.6
  Bottom Layer w10: J21.3@700,3950 653,3903 572,3903 535,3866 535,3234 569,3200 1250,3200 J20.18@1300,3250
MON2: J20.17 J21.5 | length 1524.8
  Bottom Layer w10: J21.5@700,3850 650,3800 650,3520 627,3497 572,3497 553,3478 553,3416 572,3397 632,3397 653,3376 653,3330 686.66,3296.34 791.3,3296.34 857.64,3230 1160,3230 1226.34,3296.34 1319.19,3296.34 1335.53,3280 1370,3280 J20.17@1400,3250
MON3: J20.16 J21.7 | length 909.5
  Top Layer w10: J21.7@700,3750 653,3703 653,3618 674,3597 719,3597 966,3350 J20.16@1300,3350
MON4: J20.15 J21.9 | length 824.3
  Top Layer w10: J21.9@700,3650 950,3400 1317.91,3400 1339.8,3378.11 1371.89,3378.11 J20.15@1400,3350
MON5: J20.14 J21.11 | length 1195.3
  Bottom Layer w10: J21.11@700,3550 840,3690 1142.05,3690 1194.17,3637.87 1237.4,3637.87 1271.62,3603.66 1319.19,3603.66 1335.53,3620 1364.47,3620 1380.81,3603.66 1413.34,3603.66 1447,3570 1447,3414 1436,3403 1347,3403 J20.14@1300,3450
MON6: J20.13 J21.13 | length 788.6
  Bottom Layer w10: J21.13@700,3450 760,3390 1060,3390 1167,3497 1353,3497 J20.13@1400,3450
MON7: J20.12 J21.15 | length 863.4
  Bottom Layer w10: J21.15@700,3350 671.72,3378.28 671.72,3400.82 653,3419.54 653,3474 682,3503 773,3503 870,3600 1250,3600 J20.12@1300,3550
MON8: J20.11 J22.1 | length 1045.5
  Top Layer w10: J20.11@1400,3550 1946.34,4096.34 2153.66,4096.34 J22.1@2200,4050
MON9: J20.10 J22.3 | length 1267.3
  Bottom Layer w10: J20.10@1300,3650 1253,3697 1253,3880.66 1276,3903.66 1446,3903.66 1542.34,4000 2150,4000 J22.3@2200,3950
MON10: J20.9 J22.5 | length 1248.2
  Bottom Layer w10: J20.9@1400,3650 1550,3500 2131,3500 2153,3522 2153,3582 2171,3600 2236,3600 2246.34,3610.34 2246.34,3803.66 J22.5@2200,3850
MON11: J20.8 J22.7 | length 938.9
  Bottom Layer w10: J20.8@1300,3750 1347,3797 2153,3797 J22.7@2200,3750
MON12: J20.7 J22.9 | length 880.4
  Bottom Layer w10: J20.7@1400,3750 1547,3603 2135.79,3603 2154.51,3621.72 2171.72,3621.72 J22.9@2200,3650
MON13: J20.6 J22.11 | length 1672
  Top Layer w10: J20.6@1300,3850 1350,3800 1534,3800 1848.21,4114.21 2230.79,4114.21 2247,4098 2247,3597 J22.11@2200,3550
MON14: J20.5 J22.13 | length 1333.7
  Bottom Layer w10: J20.5@1400,3850 1452.73,3850 1499.73,3897 2224,3897 2264.21,3856.79 2264.21,3514.21 J22.13@2200,3450
MON15: J20.4 J22.15 | length 1497.3
  Top Layer w10: J20.4@1300,3950 1253,3903 1253,3714 1270,3697 1324,3697 1353.66,3667.34 1353.66,3421.34 1372,3403 v1(1718,3403)
  Bottom Layer w10: v1(1718,3403) 2147,3403 J22.15@2200,3350
N2HET1_0/MIBSPI4CLK/EPWM2B: J10.20 J11.19 J16.1 | length 4991.7
  Top Layer w10: v1(1028,434) 1028,910 1050,932 J11.19@1050,1050
  Bottom Layer w10: J16.1@300,1950 247,1897 172,1897 153,1878 153,1218 171,1200 787,1200 890,1097 1003,1097 J11.19@1050,1050 ; v1(1028,434) 912.39,318.39 816.39,318.39 796,298 796,244.61 783,231.61 732,231.61 694,269.61 694,293 668,319 619,319 606,306 606,226 638,194 2369,194 J10.20@2450,275
N2HET1_1/MIBSPI4NENA/N2HET2_8/EQEP2A: J6.2 J10.21 J11.18 J13.11 J18.9 | length 6602.1
  Top Layer w10: v1(2296,1096) 2537.13,854.87 2537.13,644 2550,631.13 J10.21@2550,275 ; J13.11@2550,1450 2597,1403 2597,1314.21 2614.21,1297 2614.21,339.21 J10.21@2550,275 ; J6.2@3750,2425 3706.13,2381.13 3625.13,2381.13 3606,2362 3606,1856 J18.9@3300,1550 3388.21,1461.79 3388.21,1041.21 3003,656 3003,258 2976,231 2594,231 J10.21@2550,275
  Bottom Layer w10: J11.18@950,1150 982.89,1117.11 1014.21,1117.11 1034.32,1097 2295,1097 v1(2296,1096)
N2HET1_2/MIBSPI4SIMO/EPWM3A: J4.1 J11.17 J16.3 | length 2263.2
  Top Layer w10: J11.17@1050,1150 1150,1250 J4.1@1150,2325
  Bottom Layer w10: J16.3@300,1850 775,2325 J4.1@1150,2325
N2HET1_3/MIBSPI4NCS_0/N2HET2_10/EQEP2B: J10.22 J11.16 J13.9 J18.11 | length 4846
  Top Layer w10: J13.9@2550,1550 2650,1450 J10.22@2650,275
  Bottom Layer w10: J11.16@950,1250 997,1203 1238.25,1203 1269.13,1172.13 1328.87,1172.13 1336.75,1180 1664.47,1180 1680.81,1196.34 1719.19,1196.34 1735.53,1180 1764.47,1180 1780.81,1196.34 1893.66,1196.34 1960,1130 2320,1130 2347,1103 2478,1103 2497,1122 2497,1378 2516,1397 3214.91,1397 3232.13,1414.21 3264.21,1414.21 J18.11@3300,1450 3271.89,1478.11 3257.67,1478.11 3235.79,1500 2600,1500 J13.9@2550,1550
N2HET1_4/MIBSPI4NCS_1/EPWM4B: J1.9 J11.15 J16.5 | length 4922.9
  Top Layer w10: J16.5@300,1750 253,1703 253,850 450,653 450,258.22 514.22,194 1162,194 1194,226 1194,290 1226,322 1647,322 1906,581 ; v1(1299,1202) 1299,916 1206,823 1206,703 1228,681 1372,681 1394,659 1394,607 1420,581 1906,581 ; J1.9@1950,625 1906,581
  Bottom Layer w10: J11.15@1050,1250 1251,1250 v1(1299,1202)
N2HET1_5/MIBSPI4SOMI/N2HET2_12/EPWM3B: J10.25 J11.14 | length 3111.5
  Top Layer w10: J11.14@950,1350 885.79,1285.79 885.79,972.79 v1(955.57,903) ; J10.25@2950,275 v1(2950,880)
  Bottom Layer w10: v1(955.57,903) 978.57,880 v1(2950,880)
N2HET1_6/SCI3RX/EPWM5A: J1.3 J11.13 J16.7 | length 3731.2
  Top Layer w10: J16.7@300,1650 492,1458 492,253.28 514.28,231 1017,231 ; J11.13@1050,1350 1003,1303 1003,468.75 998.13,463.87 998.13,249.87 1017,231 ; J1.3@1350,625 1106,381 1106,258 1074,226 1022,226 1017,231
N2HET1_7/MIBSPI4NCS_2/N2HET2_14/EPWM7B: J10.28 J11.12 | length 3587.5
  Top Layer w10: v1(934,992) 903.66,1022.34 903.66,1269.2 937.46,1303 973,1303 997,1327 997,1403 J11.12@950,1450 ; J10.28@3250,275 3326,351 v1(3326,817)
  Bottom Layer w10: v1(934,992) 1010.17,915.83 3227.17,915.83 v1(3326,817)
N2HET1_8/MIBSPI1SIMO_1/MII_TXD_3: J8.3 J11.11 J16.9 | length 5026.9
  Top Layer w10: v1(1000,1800) 1000,1500 J11.11@1050,1450 ; J8.3@3850,2325 3888.25,2363.25 3888.25,2386.75 3894,2392.5 v1(3894,2581)
  Bottom Layer w10: J16.9@300,1550 350,1500 1000,1500 J11.11@1050,1450 ; v1(1000,1800) 1000,2024 1206,2230 1206,2599 1219,2612 2909,2612 2940,2581 v1(3894,2581)
N2HET1_9/MIBSPI4NCS_3/N2HET2_16/EPWM7A: J1.10 J11.10 J14.19 | length 5538.2
  Top Layer w10: J11.10@950,1550 867.91,1467.91 867.91,906.59 969,805.5 v1(969,537) ; v1(1962,537) J1.10@2050,625 v1(2050,514) ; v1(4780,632) 4780,1030 J14.19@4800,1050
  Bottom Layer w10: v1(969,537) v1(1962,537) ; v1(2050,514) 3617.87,514 3685,581.13 4572,581.13 4641.87,651 4761,651 v1(4780,632)
N2HET1_10/MIBSPI4NCS_4/MII_TXCLK/MII_TX_AVCLK4/NTZ1_3: J8.1 J11.9 J16.11 | length 4244.2
  Bottom Layer w10: J16.11@300,1450 347,1403 1084,1403 1097,1416 1097,1503 J11.9@1050,1550 1003,1597 1003,1683 1020,1700 1126,1700 1473,2047 1473,2173 1606,2306 1606,2347 1628,2369 1884,2369 1894,2359 1894,2303 1916,2281 2072.38,2281 2116.38,2325 J8.1@3650,2325
N2HET1_11/MIBSPI3NCS_4/N2HET2_18/EPWM1SYNCO: J8.6
N2HET1_12/MIBSPI4NCS_5/MII_CRS/RMII_CRS_DV: J4.6 J11.7 J16.13 | length 2162
  Bottom Layer w10: J16.13@300,1350 347,1303 1088,1303 1115,1330 1115,1585 J11.7@1050,1650 1128.43,1650 1650,2171.57 J4.6@1650,2325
